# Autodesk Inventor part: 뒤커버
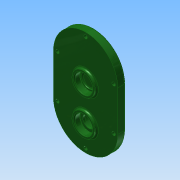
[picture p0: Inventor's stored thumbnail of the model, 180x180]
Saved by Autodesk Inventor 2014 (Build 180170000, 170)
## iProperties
Created: 2016-12
Part Number: 뒤커버
Material: 알루미늄 6061
Document SubType Name: Modeling
Designer: mduedu
Density: 2.71 g/cm^3
Appearance: 매끄러움 - 짙은 산림 녹색
Mass: 236.334 g
Surface Area: 240.96 cm^2
Volume: 87.208 cm^3
Author: mduedu
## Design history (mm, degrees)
sketch "스케치1"
  geometry: L1 (40, -25)-(40, 25); L2 (-40, 25)-(-40, -25); L3 (-40, -25)-(40, 25); L4 (40, -25)-(-40, 25); A1 r 40 centre (0, 25) between (40, 25) and (-40, 25); A2 r 40 centre (0, -25) between (-40, -25) and (40, -25); 1 further point
  constraints: 8 end point, 4 point on circle, 4 tangent, 2 centre point, 2 midpoint, 1 parallel, 1 vertical
  dimensions: "d0" = 130 dimension on A2 A1; "d2" = 80 distance between parallel lines of L1 L2
extrude "돌출1" new body sketch "스케치1" distance "d3" = 10; taper "d4" = 0 deg
sketch "스케치2"
  geometry: C1 r 14 at (0, 11); 1 further point
  constraints: 1 centre point, 1 vertical alignment
  dimensions: "d5" = 28 diameter of C1; "d6" = 11 distance of C1.centre point (0, 0)
extrude "돌출2" join sketch "스케치2" distance "d7" = 3; taper "d8" = 0 deg
sketch "스케치3"
  geometry: C1 r 14 at (0, -33.1); C2 r 14 at (0, 11) reference; 1 further point
  constraints: 1 centre point, 1 vertical alignment
  dimensions: "d9" = 28 diameter of C1; "d69" = 44.1 distance of C1.centre C2.centre
extrude "돌출3" join sketch "스케치3" distance "d11" = 3; taper "d12" = 0 deg
hole "구멍1" diameter "d15" = 22; stored, may be unused: countersink angle "d19" = 90 deg, drill point angle "d21" = 0 deg; dims "d13" = 10, "d14" = 10, "d16" = 6, "d17" = 4, "d18" = 2, "d20" = 7
hole "구멍2" diameter "d24" = 18; stored, may be unused: countersink angle "d28" = 90 deg, drill point angle "d30" = 0 deg; dims "d22" = 10, "d23" = 10, "d25" = 6, "d26" = 4, "d27" = 2, "d29" = 1
hole "구멍3" diameter "d33" = 22; stored, may be unused: countersink angle "d37" = 90 deg, drill point angle "d39" = 0 deg; dims "d31" = 10, "d32" = 10, "d34" = 6, "d35" = 4, "d36" = 2, "d38" = 7
sketch "스케치4"
  geometry: C1 r 14 at (0, -33.1) reference; C2 r 18 at (0, -33.1); 1 further point
  constraints: 1 centre point, 1 coincident
  dimensions: "d40" = 36 diameter of C2
extrude "돌출4" join sketch "스케치4" distance "d41" = 4; taper "d42" = 0 deg
hole "구멍4" diameter "d45" = 22; stored, may be unused: countersink angle "d49" = 90 deg, drill point angle "d51" = 0 deg; dims "d46" = 6, "d47" = 4, "d48" = 2, "d50" = 7.3, "d80" = 10, "d81" = 10
hole "구멍5" diameter "d54" = 15; stored, may be unused: countersink angle "d58" = 90 deg, drill point angle "d60" = 0 deg; dims "d52" = 10, "d53" = 10, "d55" = 6, "d56" = 4, "d57" = 2, "d59" = 7
fillet "모깎기1" dims "d61" = 0.3
fillet "모깎기2" dims "d62" = 2
chamfer "모따기1" distance "d63" = 1; stored, may be unused: second distance "d64" = 2, angle "d65" = 45 deg
chamfer "모따기2" distance "d82" = 0.7; stored, may be unused: second distance "d83" = 2, angle "d84" = 30 deg
fillet "모깎기3" dims "d66" = 2
fillet "모깎기4" dims "d67" = 2
fillet "모깎기5" dims "d68" = 2
sketch "스케치5"
  geometry: L1 (-40, 25)-(-40, -25) reference; L2 (40, -25)-(40, 25) reference; L3 (35, 25)-(35, -25); L4 (-35, -25)-(-35, 25); A1 r 40 centre (0, 25) between (40, 25) and (-40, 25) reference; A2 r 40 centre (0, -25) between (-40, -25) and (40, -25) reference; A3 r 35 centre (0, 25) between (35, 25) and (-35, 25); A4 r 35 centre (0, -25) between (-35, -25) and (35, -25); 2 further points
  constraints: 5 point on circle, 4 end point, 2 centre point, 1 vertical alignment, 3 other
  dimensions: "d70" = 5 distance between parallel lines of L2 L3
sketch "스케치6"
  geometry: 1 further point
  constraints: 1 other
hole "구멍6" sketch "스케치6" at (0, 60) diameter "d71" = 4.5; stored, may be unused: countersink angle "d75" = 90 deg, drill point angle "d77" = 0 deg; dims "d72" = 6, "d73" = 8, "d74" = 4.6, "d76" = 8
node "솔리드1"
pattern_linear "직사각형 패턴1"
